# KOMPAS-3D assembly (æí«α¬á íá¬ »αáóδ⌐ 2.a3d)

Referenced files in D:\АСКОН работа\Конкурс HOME\06_Сюваев_Сборная модель танка Т90\ДЕТАЛИ\КОРПУС\МЕТАЛЛ\КОРПУС ШТАМПОВКА\БАКИ\: бак правый 2.m3d
Referenced files in D:\АСКОН работа\Конкурс HOME\06_Сюваев_Сборная модель танка Т90\ДЕТАЛИ\ОБЩИЕ ДЕТАЛИ\: ручки баков.m3d
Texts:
  Сборка бак правй 2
